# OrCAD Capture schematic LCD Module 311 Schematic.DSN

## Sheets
1 01 INDEX: size A3; title: COMET LCD MODULE - Index; rev: 1.1; company: ST Microelectronics
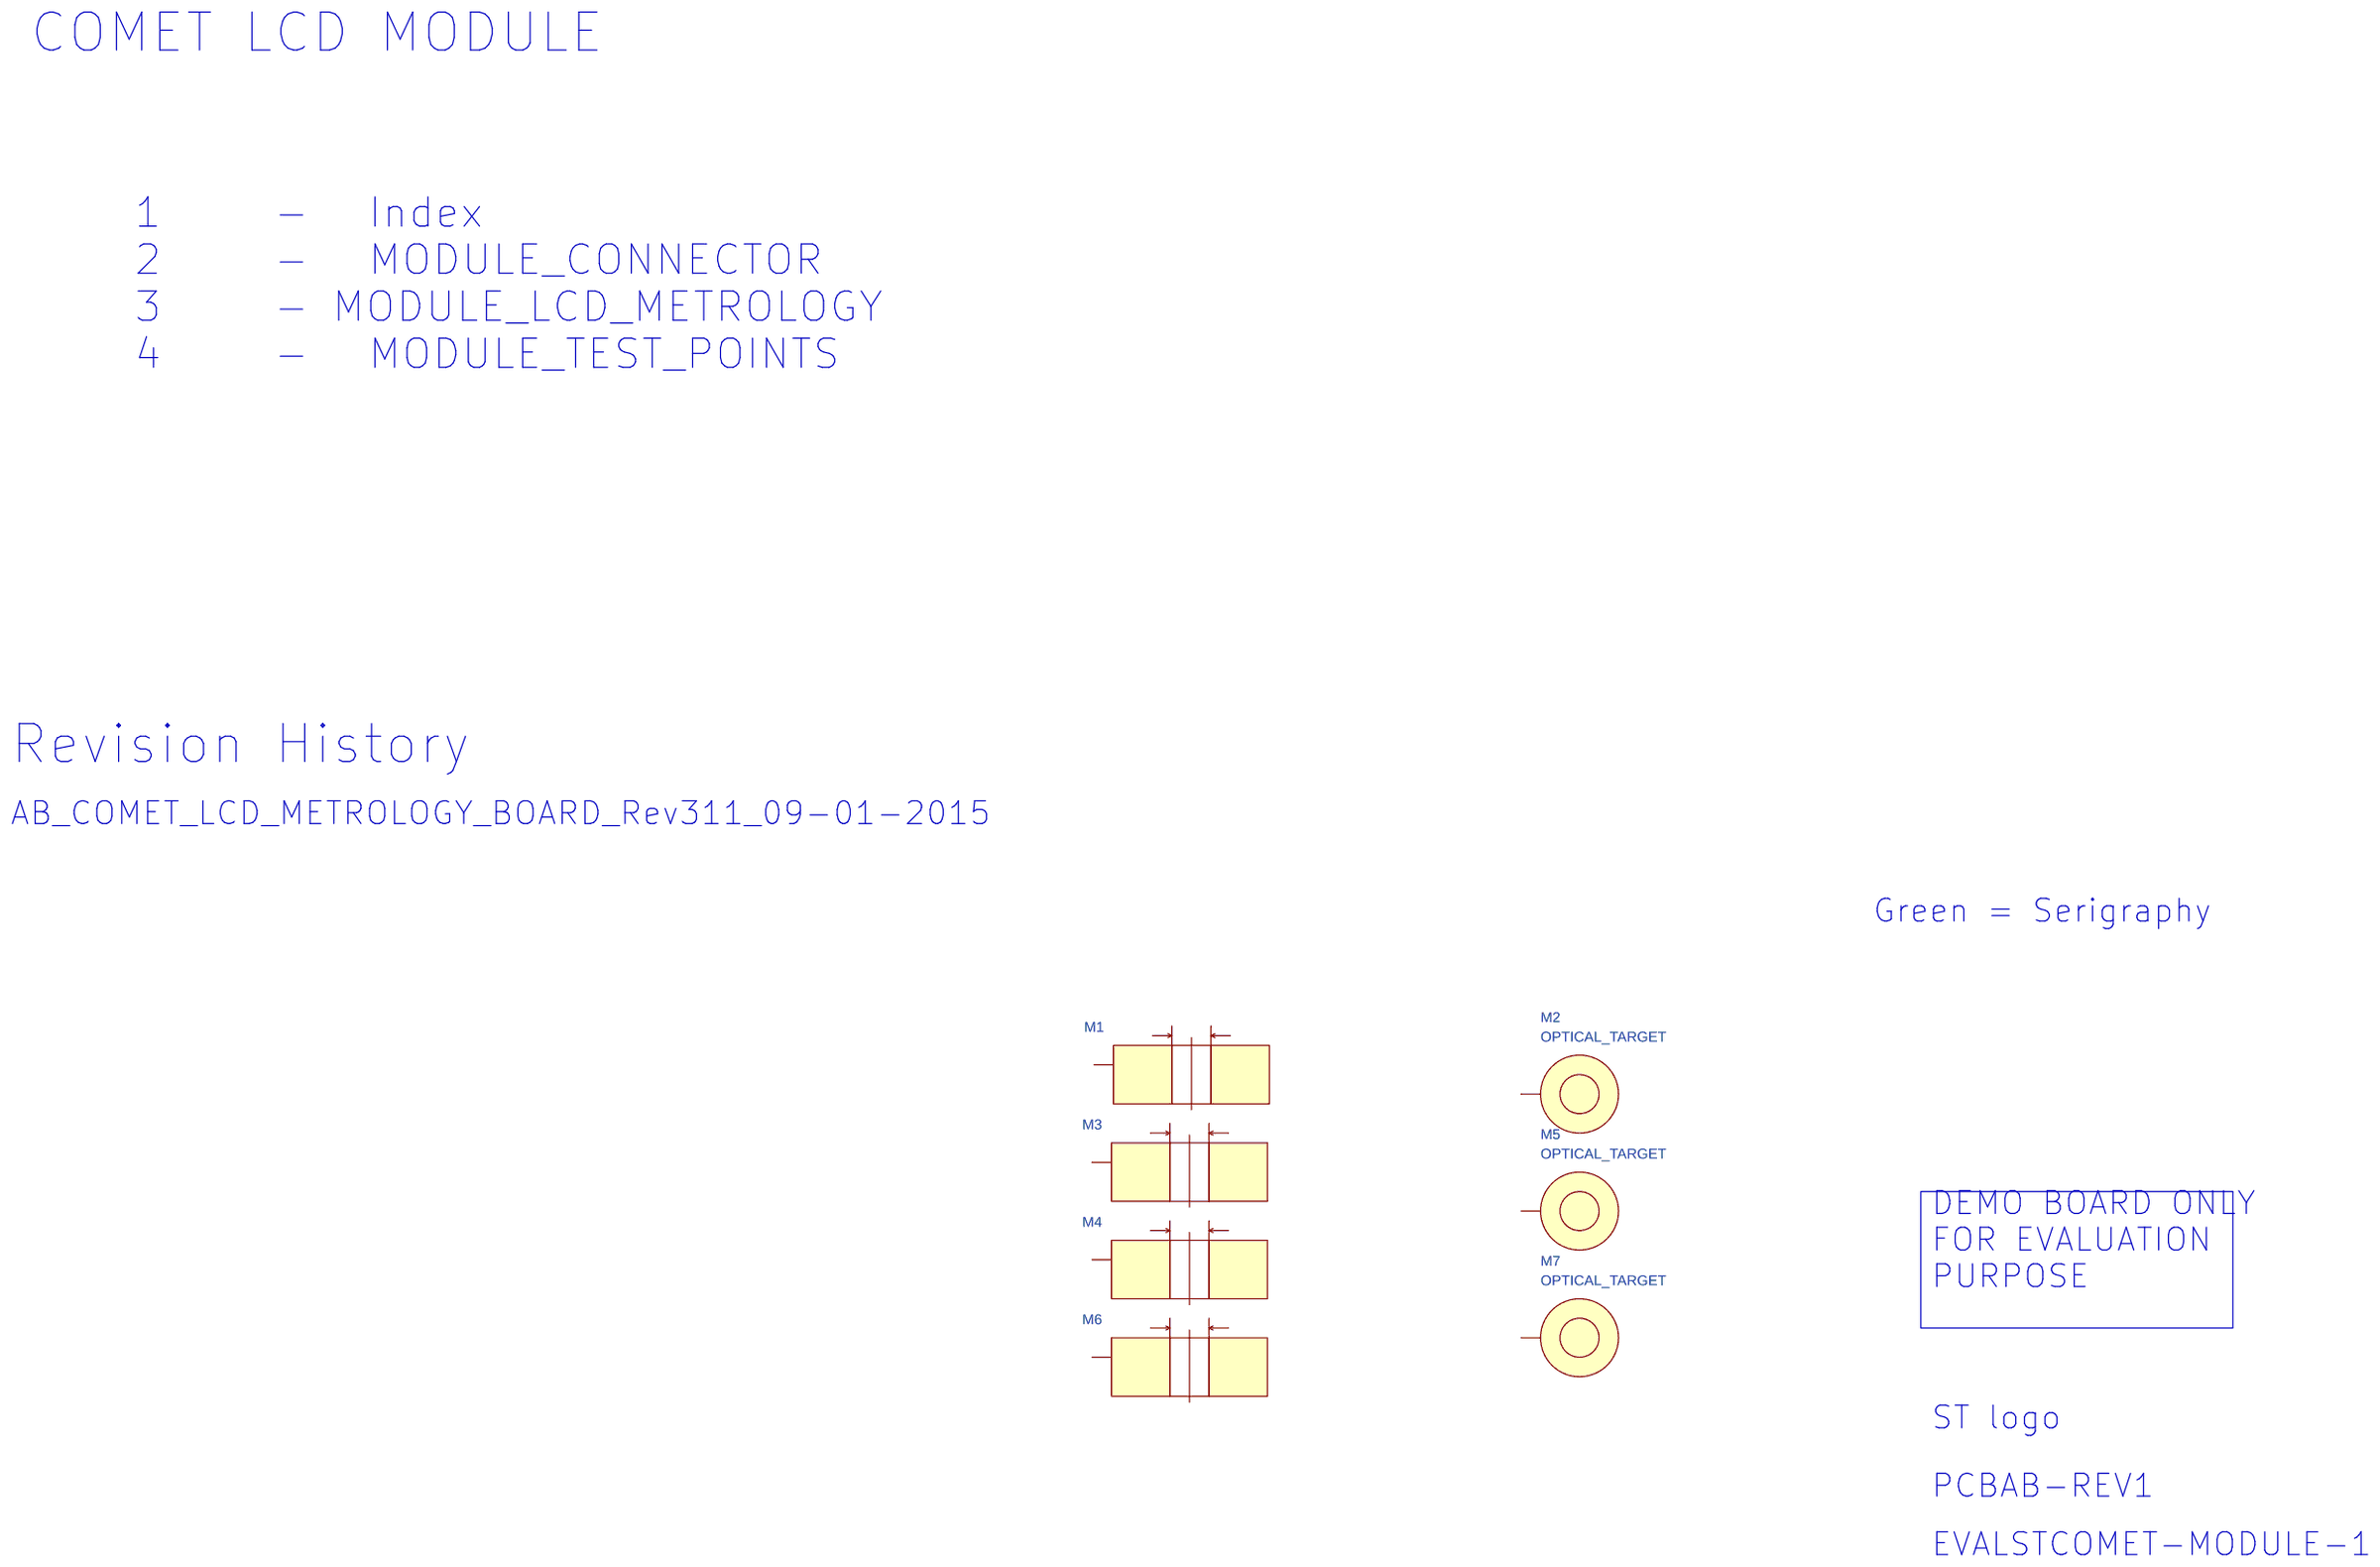
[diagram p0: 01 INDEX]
2 02 MODULE_CONNECTOR: size A3; title: MODULE connector
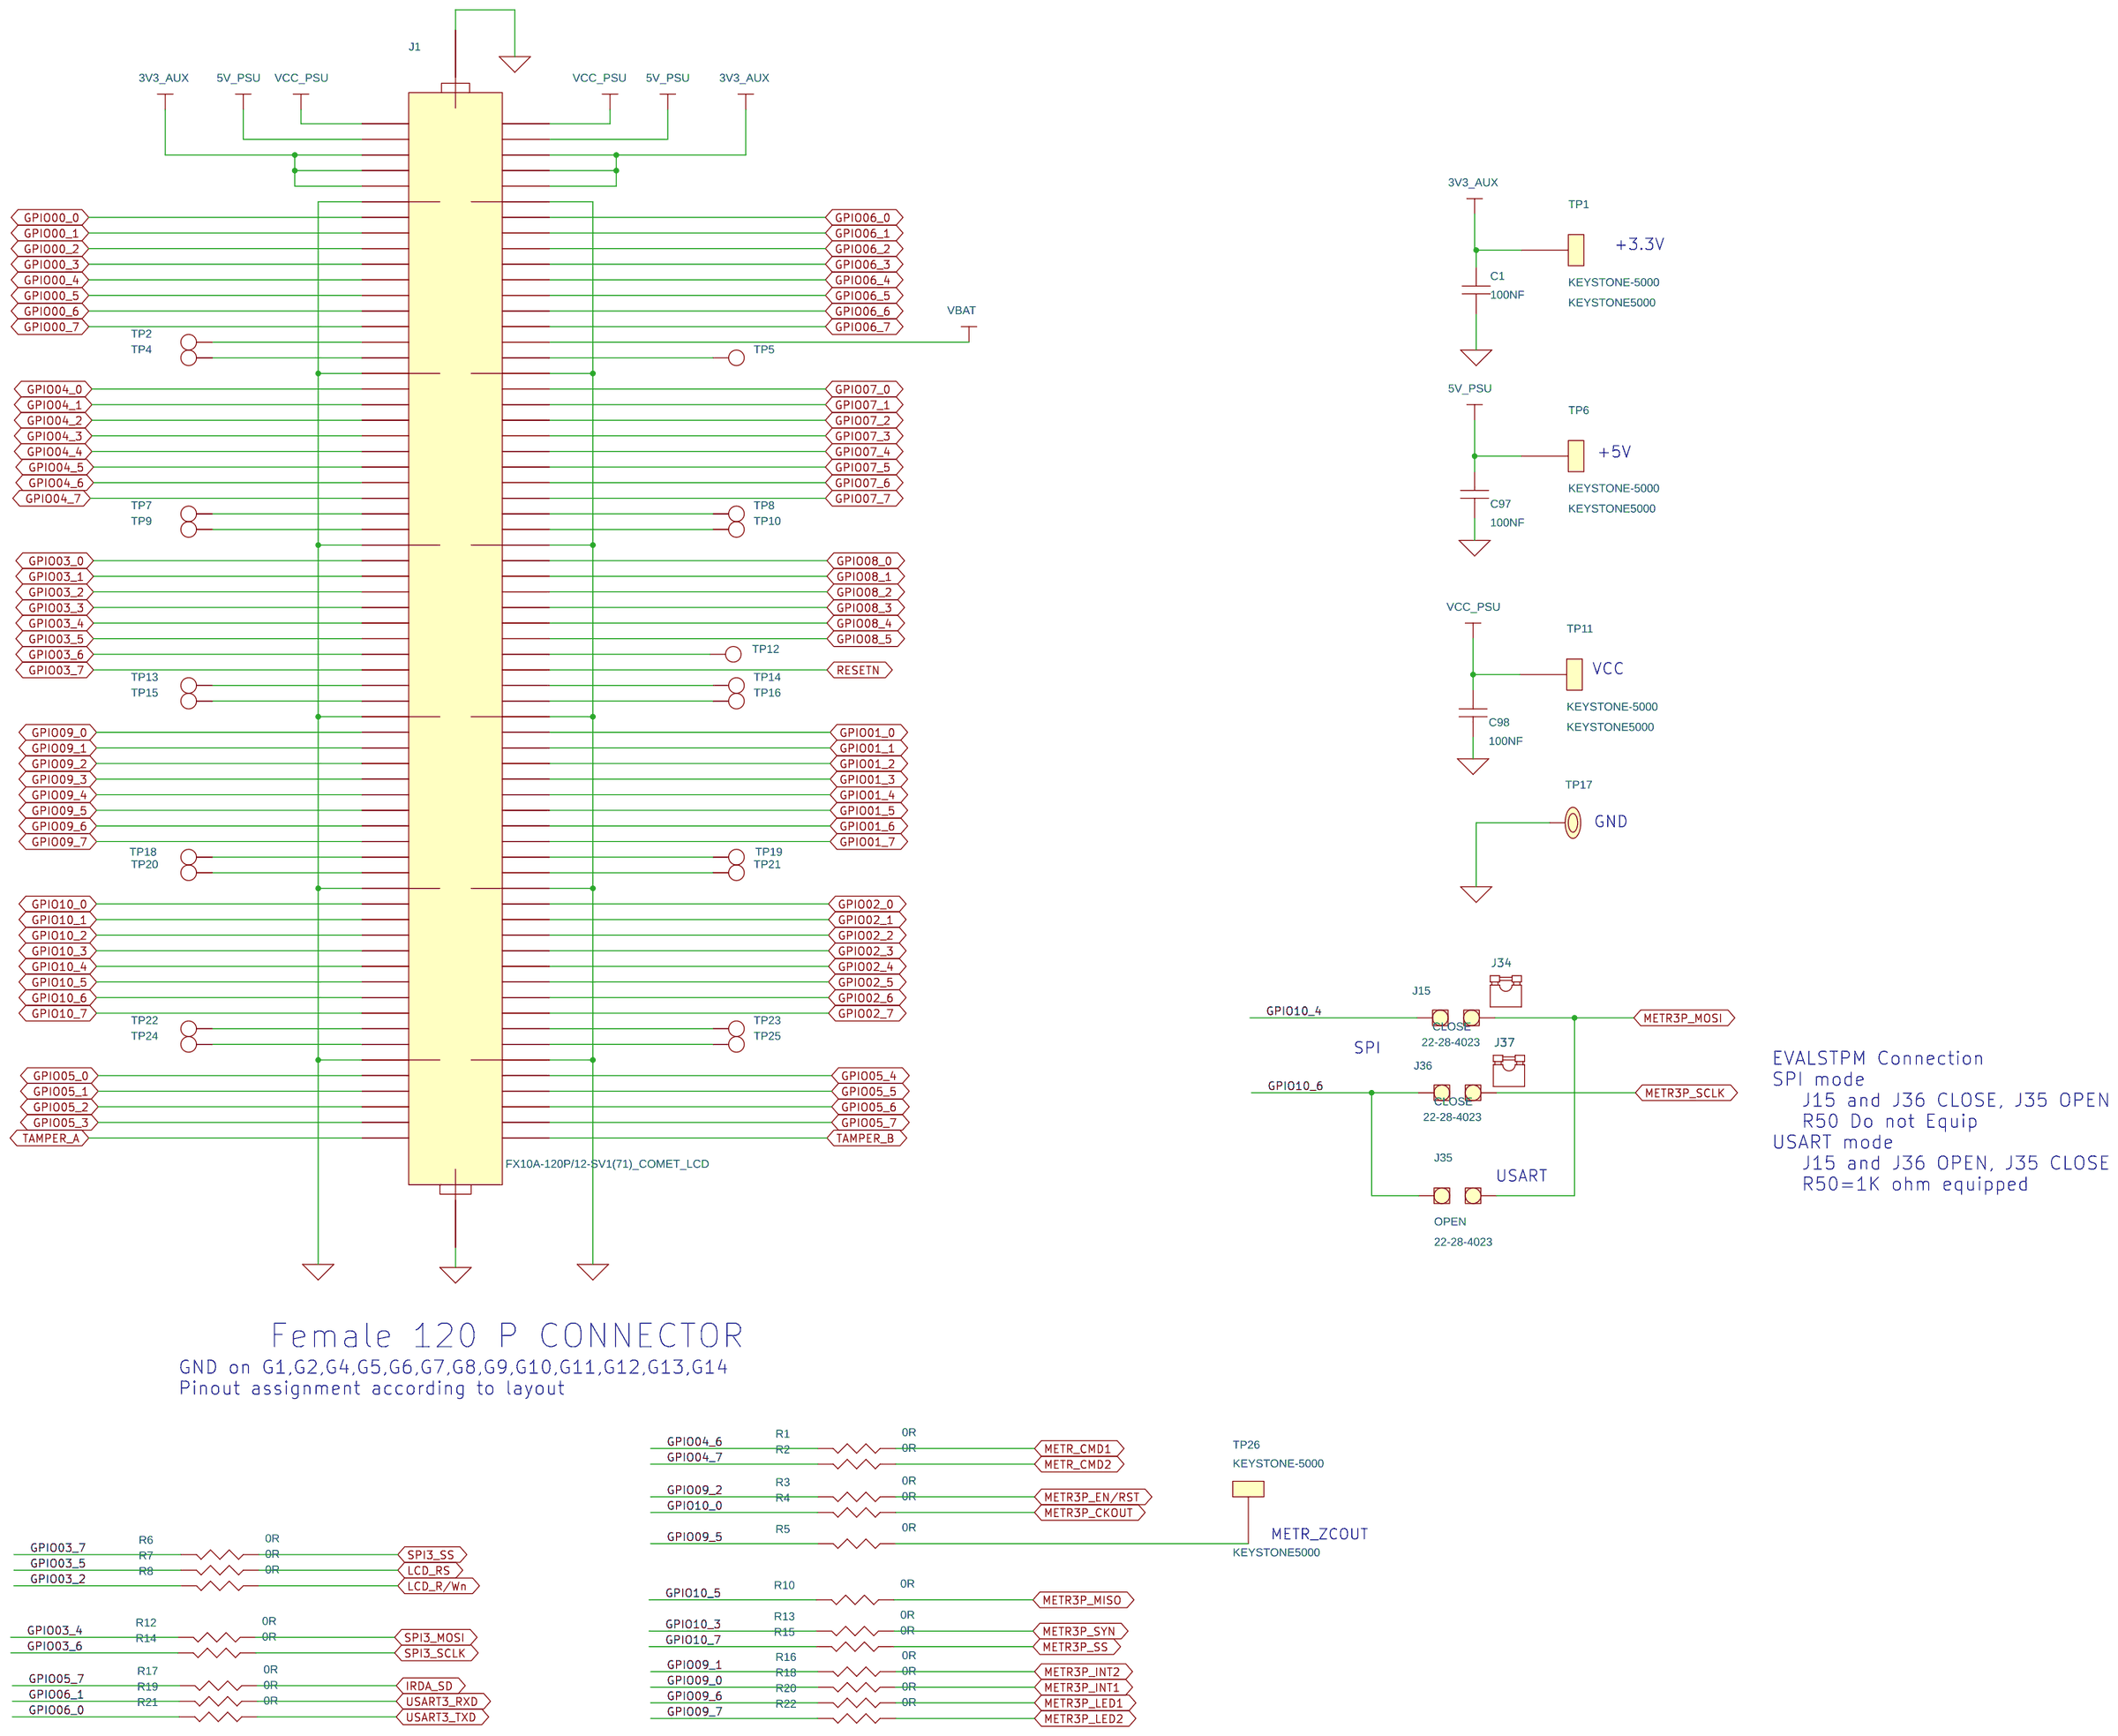
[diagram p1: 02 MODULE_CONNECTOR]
3 03 MODULE_LCD_METROLOGY: size A3; title: MODULE_METROLOGY_LCD
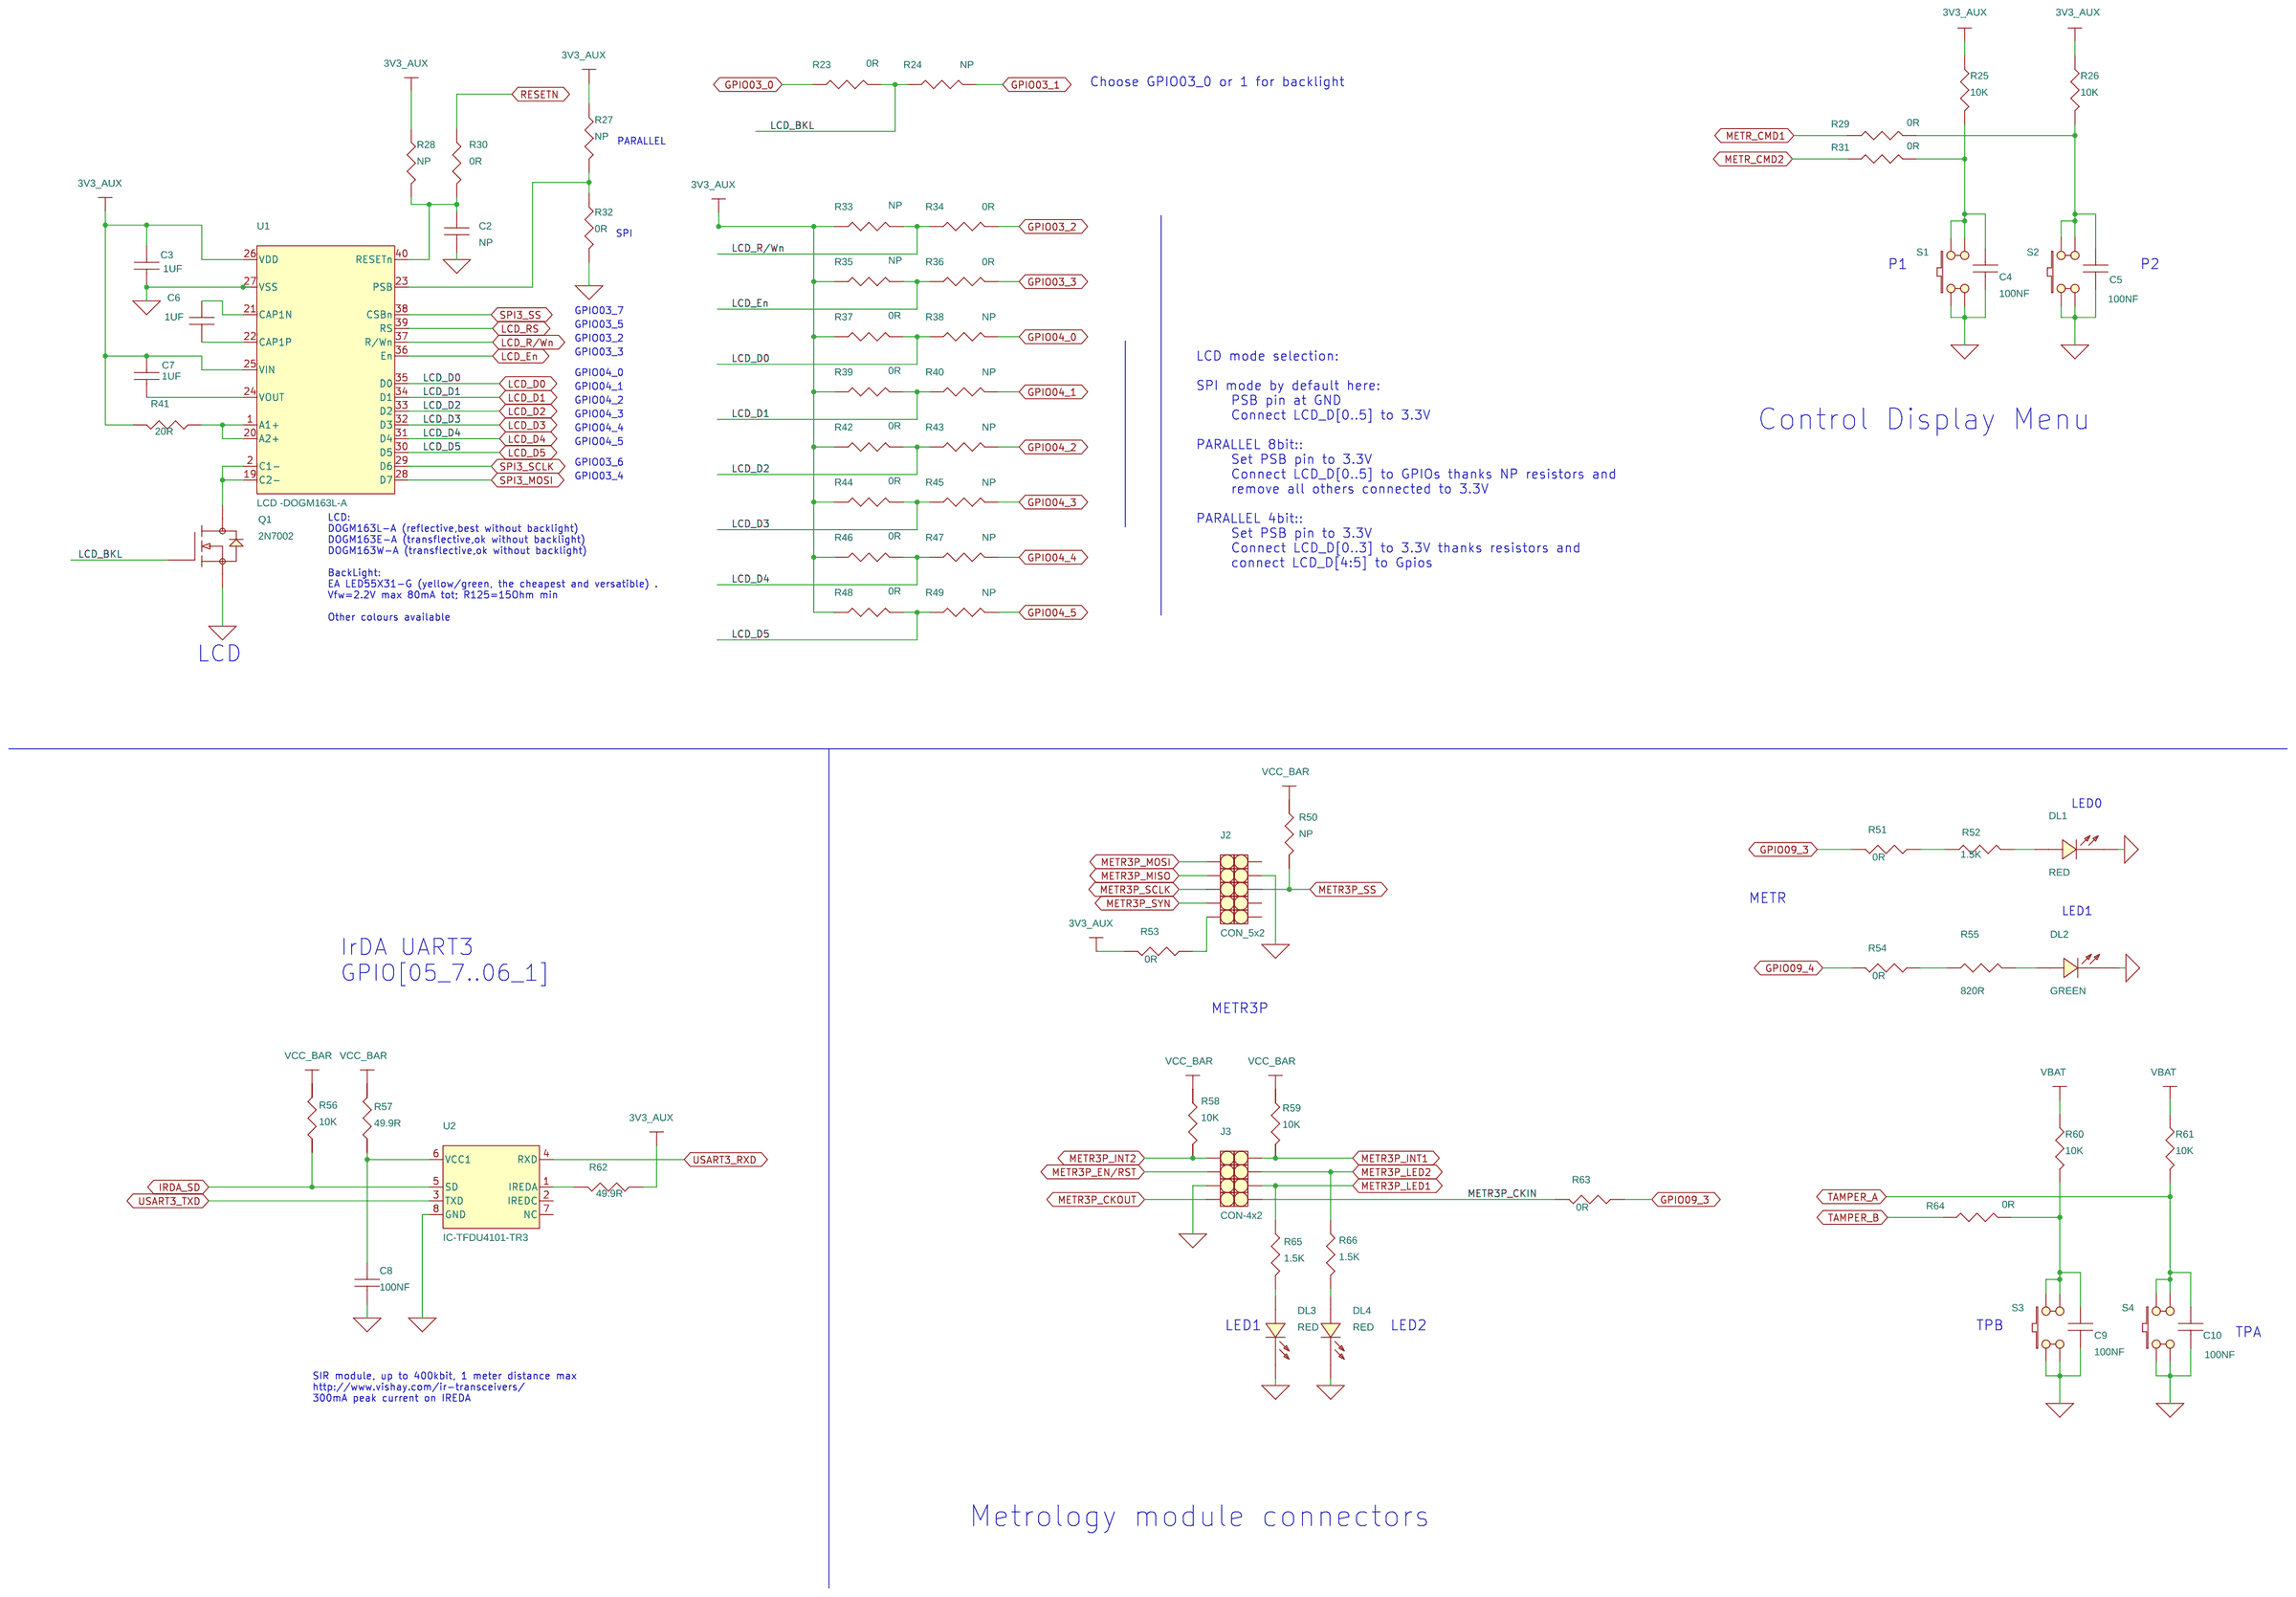
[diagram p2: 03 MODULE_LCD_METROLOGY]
4 04 MODULE_TEST_POINTS: size A3; title: MODULE_TEST_POINT
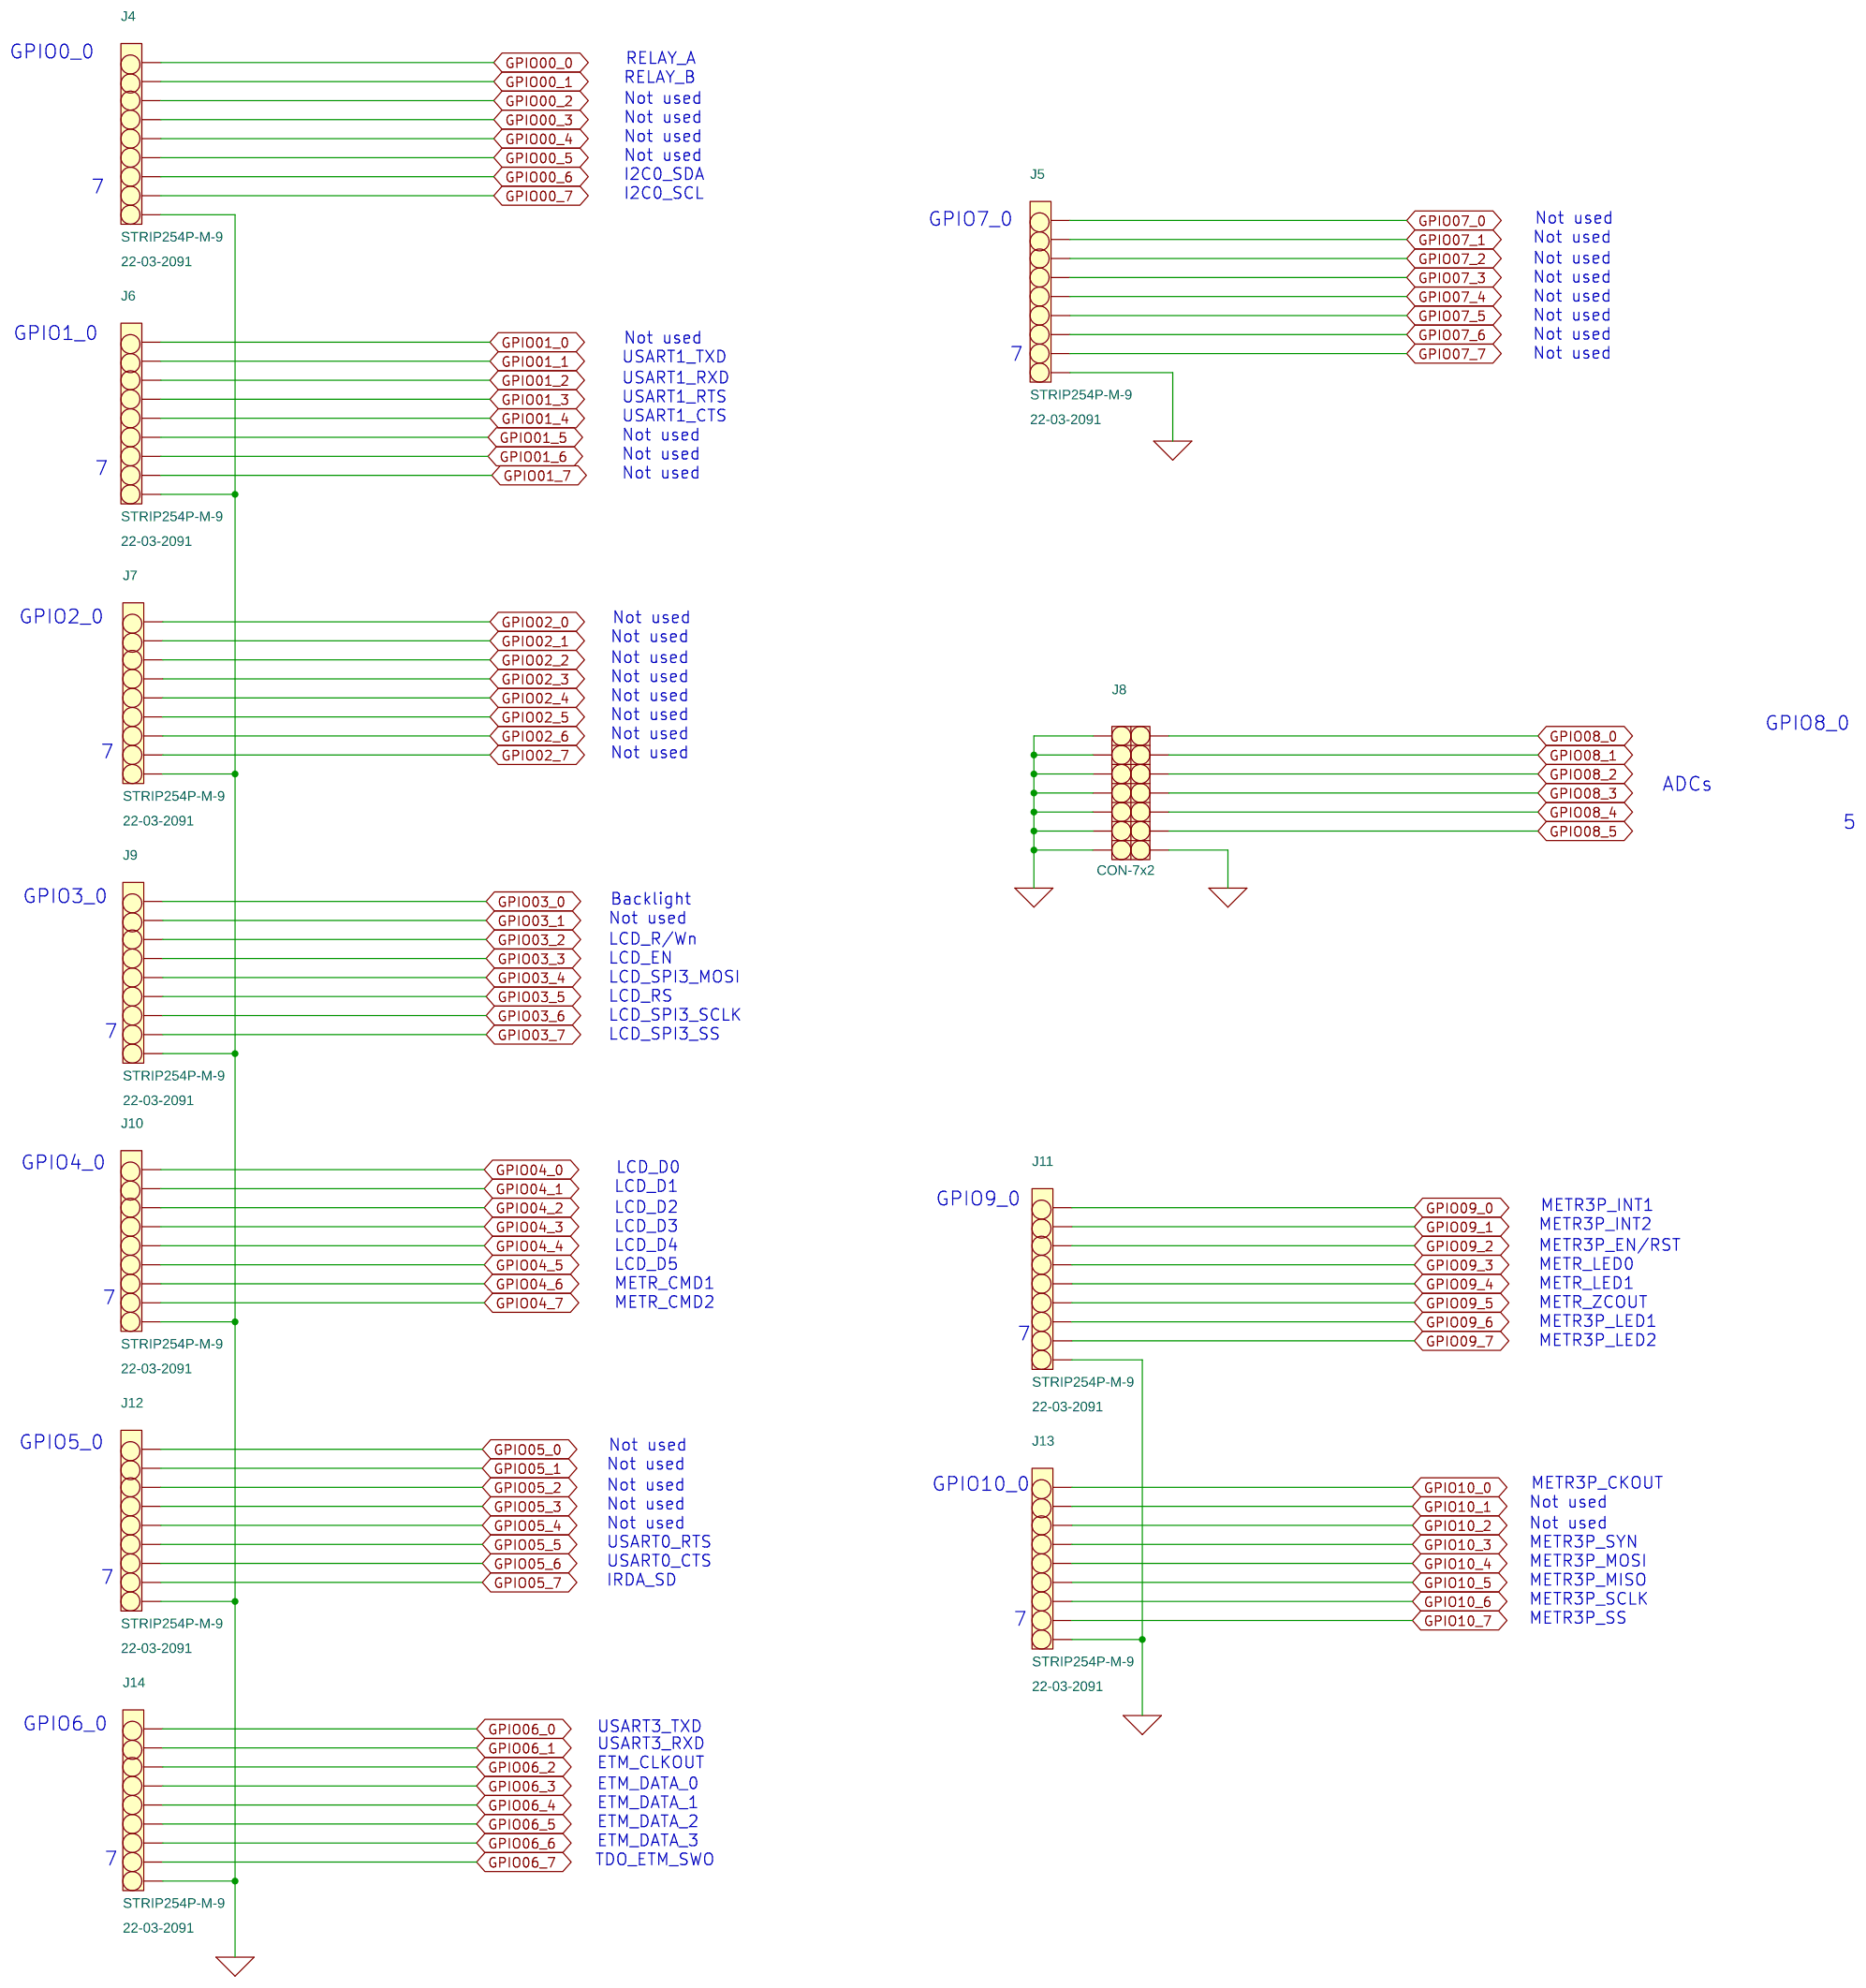
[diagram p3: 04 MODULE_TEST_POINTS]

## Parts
sheet 01 INDEX
M1  -
M2  OPTICAL_TARGET
M3  -
M4  -
M5  OPTICAL_TARGET
M6  -
M7  OPTICAL_TARGET
sheet 02 MODULE_CONNECTOR
C1  100NF  [0603]
C97  100NF  [0603]
C98  100NF  [0603]
J1  FX10A-120P/12-SV1(71)_COMET_LCD  [FX10A-120S/12-SV(71)]
J15  CLOSE  [22-28-4023]
J34  JUMPER 2.54  [JUMP254P-M-2]
J35  OPEN  [22-28-4023]
J36  CLOSE  [22-28-4023]
J37  JUMPER 2.54  [JUMP254P-M-2]
R1  0R  [0603]
R2  0R  [0603]
R3  0R  [0603]
R4  0R  [0603]
R5  0R  [0603]
R6  0R  [0603]
R7  0R  [0603]
R8  0R  [0603]
R10  0R  [0603]
R12  0R  [0603]
R13  0R  [0603]
R14  0R  [0603]
R15  0R  [0603]
R16  0R  [0603]
R17  0R  [0603]
R18  0R  [0603]
R19  0R  [0603]
R20  0R  [0603]
R21  0R  [0603]
R22  0R  [0603]
TP1  KEYSTONE-5000  [KEYSTONE5000]
TP2  TP  [TPSMD-40RD]
TP4  TP  [TPSMD-40RD]
TP5  TP  [TPSMD-40RD]
TP6  KEYSTONE-5000  [KEYSTONE5000]
TP7  TP  [TPSMD-40RD]
TP8  TP  [TPSMD-40RD]
TP9  TP  [TPSMD-40RD]
TP10  TP  [TPSMD-40RD]
TP11  KEYSTONE-5000  [KEYSTONE5000]
TP12  TP  [TPSMD-40RD]
TP13  TP  [TPSMD-40RD]
TP14  TP  [TPSMD-40RD]
TP15  TP  [TPSMD-40RD]
TP16  TP  [TPSMD-40RD]
TP17  TP  [TPTH-ANELLO-1MM]
TP18  TP  [TPSMD-40RD]
TP19  TP  [TPSMD-40RD]
TP20  TP  [TPSMD-40RD]
TP21  TP  [TPSMD-40RD]
TP22  TP  [TPSMD-40RD]
TP23  TP  [TPSMD-40RD]
TP24  TP  [TPSMD-40RD]
TP25  TP  [TPSMD-40RD]
TP26  KEYSTONE-5000  [KEYSTONE5000]
sheet 03 MODULE_LCD_METROLOGY
C2  NP  [0603]
C3  1UF  [0603]
C4  100NF  [0603]
C5  100NF  [0603]
C6  1UF  [0603]
C7  1UF  [0603]
C8  100NF  [0603]
C9  100NF  [0603]
C10  100NF  [0603]
DL1  RED  [3mm TH]
DL2  GREEN  [3mm TH]
DL3  RED  [3mm TH]
DL4  RED  [3mm TH]
J2  CON_5x2  [STRIP254P-M-5x2]
J3  CON-4x2  [STRIP254P-M-4x2]
Q1  2N7002  [SOT23-3L]
R23  0R  [0603]
R24  NP  [0603]
R25  10K  [0603]
R26  10K  [0603]
R27  NP  [0603]
R28  NP  [0603]
R29  0R  [0603]
R30  0R  [0603]
R31  0R  [0603]
R32  0R  [0603]
R33  NP  [0603]
R34  0R  [0603]
R35  NP  [0603]
R36  0R  [0603]
R37  0R  [0603]
R38  NP  [0603]
R39  0R  [0603]
R40  NP  [0603]
R41  20R  [0603]
R42  0R  [0603]
R43  NP  [0603]
R44  0R  [0603]
R45  NP  [0603]
R46  0R  [0603]
R47  NP  [0603]
R48  0R  [0603]
R49  NP  [0603]
R50  NP  [0603]
R51  0R  [0603]
R52  1.5K  [0603]
R53  0R  [0603]
R54  0R  [0603]
R55  820R  [0603]
R56  10K  [0603]
R57  49.9R  [0603]
R58  10K  [0603]
R59  10K  [0603]
R60  10K  [0603]
R61  10K  [0603]
R62  49.9R  [0603]
R63  0R  [0603]
R64  0R  [0603]
R65  1.5K  [0603]
R66  1.5K  [0603]
S1  EVQPAC04M  [BUTTON-EVQPA]
S2  EVQPAC04M  [BUTTON-EVQPA]
S3  EVQPAC04M  [BUTTON-EVQPA]
S4  EVQPAC04M  [BUTTON-EVQPA]
U1  LCD -DOGM163L-A
U2  IC-TFDU4101-TR3  [SMD Irda]
sheet 04 MODULE_TEST_POINTS
J4  STRIP254P-M-9  [22-03-2091]
J5  STRIP254P-M-9  [22-03-2091]
J6  STRIP254P-M-9  [22-03-2091]
J7  STRIP254P-M-9  [22-03-2091]
J8  CON-7x2  [STRIP254P-M-7X2]
J9  STRIP254P-M-9  [22-03-2091]
J10  STRIP254P-M-9  [22-03-2091]
J11  STRIP254P-M-9  [22-03-2091]
J12  STRIP254P-M-9  [22-03-2091]
J13  STRIP254P-M-9  [22-03-2091]
J14  STRIP254P-M-9  [22-03-2091]

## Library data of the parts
M1 M3 M4 M6 = HOLE
M2 M5 M7 = OPTICAL_TARGET
C1 C8 = CAP_NP: CAP CER 100nF 50V X7R 0603; Manufacturer: MURATA; Manufacturer Part Number: GRM188R71H104KA93D; PSpice: C; Package_Type: C0603; Part Number: GRM188R71H104KA93D; Part Type: CERAMIC; Tolerance: 5%; Voltage: 50V; Datasheet: http://www.farnell.com/datasheets/1692833.pdf
C4 C5 C9 C10 C97 C98 = CAP_NP: CAP CER 100nF 50V X7R 0603; PSpice: C; Package_Type: C0603; Part Number: 100NF_50V_X7R_0603; Part Type: CERAMIC; Tolerance: 15%; Voltage: 50V; Datasheet: http://www.farnell.com/datasheets/1692833.pdf
J1 = CON-FX10-120P-F-GND: CONN 120P high density EMBASE MALE. 0.5MM. GUIDE. 120 VOIES specific COMET with Package Type of FX10A-120S due to EMS error; Manufacturer: HIROSE; Manufacturer Part Number: FX10A-120P/12-SV1; Package_Type: FX10A-120S/12-SV; Datasheet: \\pouilly.rns.st.com\home\_RDC\External_DataSheet\Connectors\Board_to_Board\Hirose\FXxx\en_FX10_20110101.pdf
J15 J36 = JUMP254P-M-2: Manufacturer: MOLEX; Package_Type: JUMPER-CLOSE; Part Number: 22-28-4023_C; Datasheet: http://www.molex.com/pdm_docs/sd/022284023_sd.pdf
J34 J37 = JUMP-Female-2P-MetalContact: JUMPER FEMALE METAL CONTACT; Distributor: RS; Distributor Part Number: 481-0738; Manufacturer: KONTEL; Manufacturer Part Number: ETAME 3131730000430; Datasheet: http://de.rs-online.com/web/p/jumper-und-shunts/4810738/
J35 = JUMP254P-M-2: Manufacturer: MOLEX; Package_Type: JUMPER-OPEN; Part Number: 22-28-4023_O; Datasheet: http://www.molex.com/pdm_docs/sd/022284023_sd.pdf
R1-R8 R10 R12-R23 R29-R32 R34 R36 R37 R39 R42 R44 R46 R48 R51 R53 R54 R63 R64 = R: 0.0 OHM 5% 1/10W 0603; Manufacturer: YAGEO; Manufacturer Part Number: RC0603JR-070RL; Package_Type: R0603; Part Number: RC0603JR-070RL; Part type: CMS; Power: 1/10W; Tolerance: 5%
TP1 TP6 TP11 TP26 = TEST_POINT: TEST POINT RED; Distributor: FARNELL; Distributor Part Number: 1463076; Manufacturer: KEYSTONE; Manufacturer Part Number: KEYSTONE 5000; Part Number: KEYSTONE 5000; Datasheet: http://www.keyelco.com/category.cfm/keyelco/Terminals-Terminal-Boards/id/509
TP2 TP4 TP5 TP7-TP10 TP12-TP16 TP18-TP25 = TPSMD-40RD: Point Test PCB TPSMD-40RD
TP17 = TPTH-ANELLO-1MM: Point Test TPTH-ANELLO-1MM black; Distributor: FARNELL; Distributor Part Number: 1463077; Manufacturer: KEYSTONE; Manufacturer Part Number: 534-5001; Datasheet: http://fr.farnell.com/keystone/5001/test-point-connector-black/dp/1463077?Ntt=534-5001
C2 = CAP_NP: CAP NP 0603; PSpice: C; Package_Type: C0603; Part Number: C_NP_0603
C3 C6 C7 = CAP_NP: CAP CER 1UF 25V X5S 0603; Manufacturer: AVX; Manufacturer Part Number: ECJ1V41E105M; PSpice: C; Package_Type: C0603; Part Number: ECJ1V41E105M; Part Type: CERAMIC; Tolerance: 20%; Voltage: 25V
DL1 DL3 DL4 = LED: RED LED Through Hole 3mm; Distributor: FARNELL; Distributor Part Number: 1020608; Manufacturer: VISHAY; Manufacturer Part Number: TLLR4401; Package_Type: LED_TRAD_DROIT_3MM; Part Number: LED_RED_3mm_2mA; Datasheet: http://www.vishay.com/docs/83029/tllg440.pdf
DL2 = LED: GREEN LED Through Hole 3mm; Distributor: FARNELL; Distributor Part Number: 1045505; Manufacturer: VISHAY; Manufacturer Part Number: TLLG4401; Package_Type: LED_TRAD_DROIT_3MM; Part Number: LED_GREEN_3mm_2mA; Datasheet: http://www.farnell.com/datasheets/1747525.pdf
J2 = STRIP254P-M-5x2: Manufacturer: MOLEX; Manufacturer Part Number: 2213S-10G; Package_Type: CON-MOLEX-2213S-10G; Part Number: 2213S-10G
J3 = STRIP254P-M-4x2: Manufacturer: MOLEX; Manufacturer Part Number: 2213S-8G; Package_Type: CON-MOLEX-2213S-08G; Part Number: 2213S-8G
Q1 = MPF6661: TRANSISTOR - N-FET - POWER MOSLow Voltage lN-CHANNEL 60V - 1.8 Ohm - 0.35A SOT23-3L; ICA_MFR_NAME: STMICROELECTRONICS; ICA_PARTNUM: $$2142669$$2N7002; Manufacturer: FAIRCHILD; PSpice: T; Package_type: 2N7002-SOT23; Rating: 60V; Datasheet: http://www.fairchildsemi.com/ds/2N/2N7000.pdf
R24 R27 R28 R33 R35 R38 R40 R43 R45 R47 R49 R50 = R: RES NP 0603; Package_Type: R0603; Part Number: R_NP_0603; Part type: CMS
R25 R26 R60 R61 = R: RES 10K OHM 5% 1/10W 0603 SMD; Package_Type: R0603; Part Number: 10K_5%_0603; Part type: CMS; Power: 1/10W; Tolerance: 5%
R41 = R: RES 20.0 OHM 1/10W 1% 0603 SMD; ActivepartsID: http://CDS2.ORCAD.COM/default.asp?PID=1784159; ICA_MFR_NAME: PANASONIC CORP; ICA_PARTNUM: $$1784159$$ERJ-3EKF20R0V; Manufacturer: PANASONIC CORP; Manufacturer Part Number: ERJ-3EKF20R0V; Package_Type: R0603; Part Number: ERJ-3EKF20R0V; Part type: CMS; Power: 1/16W; Tolerance: 1%; Datasheet: http://www.panasonic.com/industrial_oem/electronic_components/pdf/erj_precision.pdf
R52 R65 R66 = R: RES 1.5K OHM 1/10W 5% 0603 SMD; Distributor: FARNELL; Distributor Part Number: 2008356; Package_Type: R0603; Part Number: 1.5K_5%_0603; Part type: CMS; Power: 1/10W; Tolerance: 5%
R55 = R: 820R OHM 5% 1/10W; Package_Type: R0603; Part Number: 820R_5%_0603; Part type: CMS; Power: 1/10W; Tolerance: 5%
R56 R58 R59 = R: 10K OHM 5% 1/10W; Manufacturer: PANASONIC CORP; Manufacturer Part Number: ERJ-3GEYJ103V; Package_Type: R0603; Part Number: ERJ-3GEYJ103V; Part type: CMS; Power: 1/10W; Tolerance: 5%
R57 = R: RESISTOR,  49.9 OHM 1/16W 1% 0603 SMD; ActivepartsID: http://CDS2.ORCAD.COM/default.asp?PID=1784348; ICA_MFR_NAME: PANASONIC CORP; ICA_PARTNUM: $$1784348$$ERJ-3EKF49R9V; Manufacturer: PANASONIC CORP; Manufacturer Part Number: ERJ-3EKF49R9V; Package_Type: R0603; Part Number: ERJ-3EKF49R9V; Part type: CMS; Power: 1/16W; Tolerance: 1%; Datasheet: http://www.panasonic.com/industrial_oem/electronic_components/pdf/erj_precision.pdf
R62 = R: RES 49.9 OHM 0.1% 1/10W 0603 SMD; Distributor: DIGIKEY; Distributor Part Number: P49.9DBCT-ND; Manufacturer: PANASONIC CORP; Manufacturer Part Number: ERA-3AEB49R9V; Package_Type: R0603; Part Number: 49.9R_0.1%_0603; Part type: CMS; Power: 1/10W; Tolerance: 0.1%
S1-S4 = PULSANTE-EVQQ2_0: SWITCH BUTTON Through Hole; Distributor: Farnell; Distributor Part Number: 2284582; Manufacturer: PANASONIC CORP; Datasheet: http://www.industrial.panasonic.com/www-data/pdf/ATK0000/ATK0000CE10.pdf
U1 = LCD-DOGMxxxxx-A: DISPLAY-LCD-DOGM163L-A Equiped; Distributor: RS; Distributor Part Number: 75-8611; Manufacturer: Electronic Assembly; Manufacturer Part Number: DOGM163L-A; Package_Type: DOGM163L-A; Part Number: LCD -DOGM163L-A P; Datasheet: http://www.mouser.com/ds/2/127/dog-me-8076.pdf
U2 = IC-TFDU4101-TR3: TFDU4101-TR3 - TRANSCEIVER, INFRARED, 115.2KBPS; Manufacturer: VISHAY; Manufacturer Part Number: TFDU4101-TR3; Package_Type: TFDU4101-TR3; Part Number: TFDU4101-TR3; Datasheet: http://fr.farnell.com/jsp/search/productdetail.jsp?sku=1652524&CMP=KNC-GFR-FFR-GEN-SKU-MARGIN&mckv=sn6exwlca|pcrid|19865744822|kword|tfdu4101-tr3|match|p|plid|
J4-J7 J9-J14 = STRIP254P-M-9: Manufacturer: MOLEX
J8 = STRIP254P-M-7x2: Manufacturer: MOLEX; Manufacturer Part Number: 2213S-14G; Package_Type: CON-MOLEX-2213S-14G; Part Number: 2213S-14G

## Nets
3V3_AUX: C1.1 C3.1 C7.1 J1.5 J1.6 J1.7 J1.8 J1.9 J1.10 R25.1 R26.1 R27.1 R28.1 R33.1 R35.1 R37.1 R39.1 R41.2 R42.1 R44.1 R46.1 R48.1 R50.1 R53.1 R56.2 R57.2 R58.1 R59.1 R62.1 TP1.1 U1.25(VIN) U1.26(VDD)
5V_PSU: C97.1 J1.3 J1.4 TP6.1
GND_SIGNAL: C1.2 C2.2 C3.2 C4.2 C5.2 C8.2 C9.2 C10.2 C97.2 C98.2 DL1.1(CATHODE) DL2.1(CATHODE) DL3.1(CATHODE) DL4.1(CATHODE) J1.GND1 J1.GND2 J1.GND3 J1.GND4 J1.GND5 J1.GND6 J1.GND7 J1.GND8 J1.GND9 J1.GND10 J1.GND11 J1.GND12 J1.GND13 J1.GND14 J2.3 J3.6 J4.9 J5.9 J6.9 J7.9 J8.2 J8.4 J8.6 J8.8 J8.10 J8.12 J8.13 J8.14 J9.9 J10.9 J11.9 J12.9 J13.9 J14.9 Q1.2(S) R32.2 S1.1 S1.2 S2.1 S2.2 S3.1 S3.2 S4.1 S4.2 TP17.1 U1.27(VSS) U2.8(GND)
VBAT: J1.27 R60.1 R61.1
VCC_PSU: C98.1 J1.1 J1.2 TP11.1
GPIO00_0: J1.12 J4.1
GPIO00_1: J1.14 J4.2
GPIO00_2: J1.16 J4.3
GPIO00_3: J1.18 J4.4
GPIO00_4: J1.20 J4.5
GPIO00_5: J1.22 J4.6
GPIO00_6: J1.24 J4.7
GPIO00_7: J1.26 J4.8
GPIO01_0: J1.71 J6.1
GPIO01_1: J1.73 J6.2
GPIO01_2: J1.75 J6.3
GPIO01_3: J1.77 J6.4
GPIO01_4: J1.79 J6.5
GPIO01_5: J1.81 J6.6
GPIO01_6: J1.83 J6.7
GPIO01_7: J1.85 J6.8
GPIO02_0: J1.91 J7.1
GPIO02_1: J1.93 J7.2
GPIO02_2: J1.95 J7.3
GPIO02_3: J1.97 J7.4
GPIO02_4: J1.99 J7.5
GPIO02_5: J1.101 J7.6
GPIO02_6: J1.103 J7.7
GPIO02_7: J1.105 J7.8
GPIO03_0: J1.52 J9.1 R23.1
GPIO03_1: J1.54 J9.2 R24.2
GPIO03_2: J1.56 J9.3 R8.2 R34.2
GPIO03_3: J1.58 J9.4 R36.2
GPIO03_4: J1.60 J9.5 R12.2
GPIO03_5: J1.62 J9.6 R7.2
GPIO03_6: J1.64 J9.7 R14.2
GPIO03_7: J1.66 J9.8 R6.2
GPIO04_0: J1.32 J10.1 R38.2
GPIO04_1: J1.34 J10.2 R40.2
GPIO04_2: J1.36 J10.3 R43.2
GPIO04_3: J1.38 J10.4 R45.2
GPIO04_4: J1.40 J10.5 R47.2
GPIO04_5: J1.42 J10.6 R49.2
GPIO04_6: J1.44 J10.7 R1.2
GPIO04_7: J1.46 J10.8 R2.2
GPIO05_0: J1.112 J12.1
GPIO05_1: J1.114 J12.2
GPIO05_2: J1.116 J12.3
GPIO05_3: J1.118 J12.4
GPIO05_4: J1.111 J12.5
GPIO05_5: J1.113 J12.6
GPIO05_6: J1.115 J12.7
GPIO05_7: J1.117 J12.8 R17.2
GPIO06_0: J1.11 J14.1 R21.2
GPIO06_1: J1.13 J14.2 R19.2
GPIO06_2: J1.15 J14.3
GPIO06_3: J1.17 J14.4
GPIO06_4: J1.19 J14.5
GPIO06_5: J1.21 J14.6
GPIO06_6: J1.23 J14.7
GPIO06_7: J1.25 J14.8
GPIO07_0: J1.31 J5.1
GPIO07_1: J1.33 J5.2
GPIO07_2: J1.35 J5.3
GPIO07_3: J1.37 J5.4
GPIO07_4: J1.39 J5.5
GPIO07_5: J1.41 J5.6
GPIO07_6: J1.43 J5.7
GPIO07_7: J1.45 J5.8
GPIO08_0: J1.51 J8.1
GPIO08_1: J1.53 J8.3
GPIO08_2: J1.55 J8.5
GPIO08_3: J1.57 J8.7
GPIO08_4: J1.59 J8.9
GPIO08_5: J1.61 J8.11
GPIO09_0: J1.72 J11.1 R18.2
GPIO09_1: J1.74 J11.2 R16.2
GPIO09_2: J1.76 J11.3 R3.2
GPIO09_3: J1.78 J11.4 R51.1 R63.2
GPIO09_4: J1.80 J11.5 R54.1
GPIO09_5: J1.82 J11.6 R5.2
GPIO09_6: J1.84 J11.7 R20.2
GPIO09_7: J1.86 J11.8 R22.2
GPIO10_0: J1.92 J13.1 R4.2
GPIO10_1: J1.94 J13.2
GPIO10_2: J1.96 J13.3
GPIO10_3: J1.98 J13.4 R13.2
GPIO10_4: J1.100 J13.5 J15.1
GPIO10_5: J1.102 J13.6 R10.2
GPIO10_6: J1.104 J13.7 J35.2 J36.1
GPIO10_7: J1.106 J13.8 R15.2
IRDA_SD: R17.1 R56.1 U2.5(SD)
LCD_BKL: Q1.1(G) R23.2 R24.1
LCD_D0: R37.2 R38.1 U1.35(D0)
LCD_D1: R39.2 R40.1 U1.34(D1)
LCD_D2: R42.2 R43.1 U1.33(D2)
LCD_D3: R44.2 R45.1 U1.32(D3)
LCD_D4: R46.2 R47.1 U1.31(D4)
LCD_D5: R48.2 R49.1 U1.30(D5)
LCD_En: R35.2 R36.1 U1.36(En)
LCD_R/Wn: R8.1 R33.2 R34.1 U1.37(R/Wn)
LCD_RS: R7.1 U1.39(RS)
METR3P_CKIN: J3.7 R63.1
METR3P_CKOUT: J3.8 R4.1
METR3P_EN/RST: J3.4 R3.1
METR3P_INT1: J3.1 R18.1 R59.2
METR3P_INT2: J3.2 R16.1 R58.2
METR3P_LED1: J3.5 R20.1 R65.1
METR3P_LED2: J3.3 R22.1 R66.1
METR3P_MISO: J2.4 R10.1
METR3P_MOSI: J2.2 J15.2 J35.1
METR3P_SCLK: J2.6 J36.2
METR3P_SS: J2.5 R15.1 R50.2
METR3P_SYN: J2.8 R13.1
METR_CMD1: R1.1 R29.1
METR_CMD2: R2.1 R31.1
RESETN: J1.65 R30.1
SPI3_MOSI: R12.1 U1.28(D7)
SPI3_SCLK: R14.1 U1.29(D6)
SPI3_SS: R6.1 U1.38(CSBn)
TAMPER_A: C10.1 J1.120 R61.2 S4.3 S4.4
TAMPER_B: J1.119 R64.1
USART3_RXD: R19.1 U2.4(RXD)
USART3_TXD: R21.1 U2.3(TXD)
N21513936: C8.1 R57.1 U2.6(VCC1)
N21513983: R62.2 U2.1(IREDA)
N21514127: R41.1 U1.1(A1+) U1.20(A2+)
N21514140: Q1.3(D) U1.2(C1-) U1.19(C2-)
N21514185: J2.10 R53.2
N21514229: C7.2 U1.24(VOUT)
N21514319: C6.2 U1.22(CAP1P)
N21514321: C6.1 U1.21(CAP1N)
N21514376: DL3.2(ANODE) R65.2
N21514406: DL4.2(ANODE) R66.2
N21514497: C2.1 R28.2 R30.2 U1.40(RESETn)
N21514548: R27.2 R32.1 U1.23(PSB)
N21528760: R5.1 TP26.1
N21573309: J1.28 TP2.1
N21573580: J1.87 TP19.1
N21573594: J1.88 TP18.1
N21573654: J1.63 TP12.1
N21592870: DL1.2(ANODE) R52.1
N21592884: R51.2 R52.2
N21592886: R54.2 R55.1
N21592905: DL2.2(ANODE) R55.2
N21595537: C4.1 R25.2 R31.2 S1.3 S1.4
N21595549: C5.1 R26.2 R29.2 S2.3 S2.4
N21596041: C9.1 R60.2 R64.2 S3.3 S3.4
N21601388: J1.30 TP4.1
N21601396: J1.29 TP5.1
N21601420: J1.48 TP7.1
N21601428: J1.47 TP8.1
N21601452: J1.50 TP9.1
N21601460: J1.49 TP10.1
N21601484: J1.68 TP13.1
N21601492: J1.67 TP14.1
N21601516: J1.70 TP15.1
N21601524: J1.69 TP16.1
N21601580: J1.90 TP20.1
N21601588: J1.89 TP21.1
N21601621: J1.108 TP22.1
N21601629: J1.107 TP23.1
N21601653: J1.110 TP24.1
N21601661: J1.109 TP25.1

Not connected (* = marked no-connect by the designer): J2 1 7 9; M1 1; M2 1; M3 1; M4 1; M5 1; M6 1; M7 1; U2 2(IREDC) 7(NC)

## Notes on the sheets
sheet 1
- COMET LCD MODULE
- 1	 - 	Index
   	2	 - 	MODULE_CONNECTOR
   	3	 - MODULE_LCD_METROLOGY
   	4	 - 	MODULE_TEST_POINTS
- Revision History
- AB_COMET_LCD_METROLOGY_BOARD_Rev311_09-01-2015
- Green = Serigraphy
- DEMO BOARD ONLY
  FOR EVALUATION
  PURPOSE
- ST logo
- PCBAB-REV1
- EVALSTCOMET-MODULE-1
sheet 2
- +3.3V
- +5V
- VCC
- GND
- SPI
- EVALSTPM Connection
  SPI mode
     J15 and J36 CLOSE, J35 OPEN
     R50 Do not Equip
  USART mode
     J15 and J36 OPEN, J35 CLOSE
     R50=1K ohm equipped
- USART
- Female 120 P CONNECTOR
- GND on G1,G2,G4,G5,G6,G7,G8,G9,G10,G11,G12,G13,G14
  Pinout assignment according to layout
- METR_ZCOUT
sheet 3
- Choose GPIO03_0 or 1 for backlight
- PARALLEL
- SPI
- P1
- P2
- GPIO03_5
- GPIO03_7
- GPIO03_2
- GPIO03_3
- LCD mode selection:
  SPI mode by default here:
       PSB pin at GND
       Connect LCD_D[0..5] to 3.3V
  PARALLEL 8bit::
       Set PSB pin to 3.3V
       Connect LCD_D[0..5] to GPIOs thanks NP resistors and
       remove all others connected to 3.3V
  PARALLEL 4bit::
       Set PSB pin to 3.3V
       Connect LCD_D[0..3] to 3.3V thanks resistors and
       connect LCD_D[4:5] to Gpios
- GPIO04_0
- GPIO04_1
- GPIO04_2
- GPIO04_3
- Control Display Menu
- GPIO04_4
- GPIO04_5
- GPIO03_6
- GPIO03_4
- LCD:
  DOGM163L-A (reflective,best without backlight)
  DOGM163E-A (transflective,ok without backlight)
  DOGM163W-A (transflective,ok without backlight)
  BackLight:
  EA LED55X31-G (yellow/green, the cheapest and versatible) .
  Vfw=2.2V max 80mA tot; R125=15Ohm min
  Other colours available
- LCD
- LED0
- METR
- LED1
- IrDA UART3
  GPIO[05_7..06_1]
- METR3P
- LED1
- LED2
- TPB
- TPA
- SIR module, up to 400kbit, 1 meter distance max
  http://www.vishay.com/ir-transceivers/
  300mA peak current on IREDA
- Metrology module connectors
sheet 4
- GPIO0_0
- RELAY_A
- RELAY_B
- Not used
- Not used
- Not used
- I2C0_SDA
- Not used
- 7
- I2C0_SCL
- GPIO7_0
- Not used
- Not used
- Not used
- Not used
- Not used
- GPIO1_0
- Not used
- Not used
- 7
- Not used
- Not used
- USART1_TXD
- USART1_RTS
- USART1_RXD
- USART1_CTS
- Not used
- 7
- Not used
- Not used
- GPIO2_0
- Not used
- Not used
- Not used
- Not used
- Not used
- Not used
- Not used
- GPIO8_0
- 7
- Not used
- ADCs
- 5
- GPIO3_0
- Backlight
- LCD_R/Wn
- Not used
- LCD_EN
- LCD_SPI3_MOSI
- LCD_RS
- LCD_SPI3_SCLK
- 7
- LCD_SPI3_SS
- GPIO4_0
- LCD_D1
- LCD_D0
- LCD_D2
- GPIO9_0
- METR3P_INT1
- LCD_D3
- METR3P_INT2
- LCD_D4
- METR3P_EN/RST
- LCD_D5
- METR_LED0
- 7
- METR_CMD1
- METR_LED1
- METR_CMD2
- METR_ZCOUT
- 7
- METR3P_LED1
- METR3P_LED2
- GPIO5_0
- Not used
- Not used
- Not used
- GPIO10_0
- METR3P_CKOUT
- Not used
- Not used
- Not used
- Not used
- USART0_RTS
- METR3P_SYN
- USART0_CTS
- METR3P_MOSI
- 7
- IRDA_SD
- METR3P_MISO
- METR3P_SCLK
- 7
- METR3P_SS
- GPIO6_0
- USART3_RXD
- USART3_TXD
- ETM_CLKOUT
- ETM_DATA_0
- ETM_DATA_1
- ETM_DATA_2
- 7
- TDO_ETM_SWO
- ETM_DATA_3
